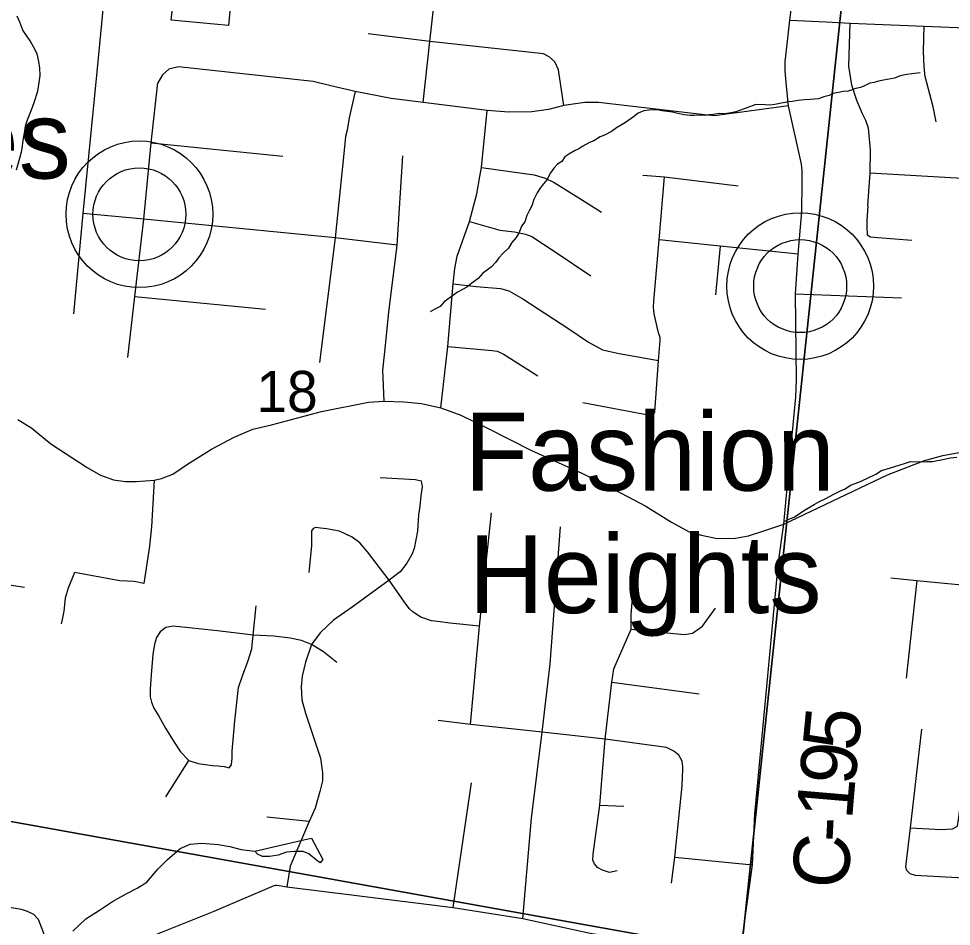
# Model space of a CAD drawing. Extents: x 0 to 43.4, y -8.1 to 22.
# Drawn here: x 6.917 to 7.863, y 16.255 to 17.176 of the extents above; entities that cross this region are included whole.
import ezdxf

# ---------------------------------------------------------------- set-up
doc = ezdxf.new("R2010")
doc.units = 0
for name, color, linetype in [('GM_X_City_Street', 7, 'Continuous'), ('GM_X_Corporation', 7, 'Continuous'), ('GM_X_County_Road', 7, 'Continuous'), ('GM_X_County_Road_Text', 7, 'Continuous'), ('GM_X_Minor_Lake', 7, 'Continuous'), ('GM_X_Minor_River', 7, 'Continuous'), ('GM_X_Section_Text', 7, 'Continuous'), ('GM_X_Township_Road', 7, 'Continuous'), ('GM_X_Unincorporated', 7, 'Continuous'), ('GM_X_Unincorporated_Location', 7, 'Continuous'), ('GM_X_Unincorporated_Text', 7, 'Continuous')]:
    doc.layers.add(name, color=color, linetype=linetype)

msp = doc.modelspace()

# ---------------------------------------------------------------- linework, layer by layer
at = {"layer": 'GM_X_City_Street'}
for points in [[(7.73626, 17.17249), (7.76063, 17.17115), (7.83577, 17.16785), (7.88622, 17.16592), (7.96008, 17.16294), (8.00847, 17.16036), (8.09018, 17.15672), (8.11414, 17.15544)], [(7.77863, 16.98558), (7.78106, 17.01914), (7.78137, 17.04256), (7.77909, 17.06442), (7.77635, 17.07212), (7.77304, 17.07888), (7.76723, 17.0924), (7.76235, 17.10796), (7.75937, 17.12729), (7.76, 17.14954), (7.76063, 17.17115)], [(7.84777, 17.07077), (7.84486, 17.08605), (7.83671, 17.11692), (7.83561, 17.12682), (7.83498, 17.14254), (7.83577, 17.16785)], [(7.78106, 17.01914), (7.90336, 17.01203), (8.00934, 17.00692), (8.1949, 17.0006)]]:
    msp.add_lwpolyline(points, dxfattribs=at)
at = {"layer": 'GM_X_Corporation'}
for points in [[(7.75749, 17.24308), (7.65014, 16.22803), (6.62666, 16.41193), (6.72714, 17.35166)], [(7.75749, 17.24308), (8.74847, 17.1931), (8.6363, 16.19901), (7.65014, 16.22803)], [(7.65014, 16.22803), (7.54379, 15.2065), (6.51942, 15.39622), (6.62666, 16.41193)]]:
    msp.add_lwpolyline(points, close=True, dxfattribs=at)
at = {"layer": 'GM_X_County_Road'}
for points in [[(7.69325, 16.66276), (7.69899, 16.72496), (7.70539, 16.79174), (7.70605, 16.80885), (7.70507, 16.89638), (7.70788, 16.93665), (7.71154, 16.97964), (7.71187, 17.00934), (7.71193, 17.0212), (7.71128, 17.02799), (7.69808, 17.08718), (7.69612, 17.10717), (7.69454, 17.12252), (7.69459, 17.13174), (7.69716, 17.15265), (7.69923, 17.17421), (7.702, 17.19538), (7.70331, 17.21681), (7.70697, 17.24634)], [(6.91604, 16.76883), (6.93026, 16.76018), (6.94963, 16.7442), (6.98628, 16.72027), (7.00013, 16.71238), (7.01331, 16.70793), (7.02541, 16.70614), (7.03602, 16.70591), (7.05445, 16.70741), (7.06188, 16.70914), (7.07336, 16.71344), (7.08837, 16.72374), (7.1126, 16.73876), (7.13563, 16.75115), (7.15439, 16.75909), (7.17345, 16.76361), (7.22418, 16.77698), (7.27172, 16.78647), (7.28795, 16.78756), (7.30777, 16.78701), (7.3258, 16.78527), (7.34544, 16.78064), (7.36548, 16.77341), (7.39279, 16.76005), (7.43714, 16.73737), (7.48837, 16.71448), (7.52179, 16.69768), (7.55343, 16.68095), (7.57917, 16.66469), (7.59712, 16.6551), (7.60993, 16.65172), (7.62577, 16.64825), (7.64437, 16.64851), (7.65733, 16.65082), (7.67302, 16.65609), (7.69325, 16.66276), (7.79836, 16.71285), (7.83608, 16.72746), (7.85463, 16.73249), (7.87491, 16.73611)], [(7.58249, 15.6055), (7.58756, 15.65514), (7.59384, 15.71421), (7.5992, 15.76453), (7.61792, 15.94053), (7.62113, 15.97245), (7.63242, 16.08479), (7.63341, 16.09461), (7.64876, 16.22421), (7.66156, 16.31734), (7.66386, 16.36899), (7.67012, 16.43335), (7.68774, 16.62457), (7.69325, 16.66276)], [(6.90828, 16.17393), (6.92096, 16.18174), (6.93139, 16.19106), (6.94814, 16.2), (7.02566, 16.23433), (7.1152, 16.27031), (7.17607, 16.29629), (7.17739, 16.29672), (7.17871, 16.29671), (7.18117, 16.29638), (7.18894, 16.29488), (7.25726, 16.28656), (7.35784, 16.27411), (7.42833, 16.26272), (7.49667, 16.24803), (7.64876, 16.22421), (7.66742, 16.22237), (7.66839, 16.22235)]]:
    msp.add_lwpolyline(points, dxfattribs=at)
at = {"layer": 'GM_X_Minor_Lake'}
for points in [[(7.15655, 16.33123), (7.20747, 16.34286), (7.21396, 16.34421), (7.21686, 16.33919), (7.22553, 16.32263), (7.22278, 16.31929), (7.21906, 16.32204), (7.21125, 16.32833), (7.20563, 16.33076), (7.19689, 16.33061), (7.18853, 16.33007), (7.18009, 16.32688)], [(7.18009, 16.32688), (7.17132, 16.32559), (7.1645, 16.32577), (7.15925, 16.32819), (7.15655, 16.33123)]]:
    msp.add_lwpolyline(points, dxfattribs=at)
at = {"layer": 'GM_X_Minor_River'}
for points in [[(6.91477, 17.02231), (6.91804, 17.03404), (6.9201, 17.04198), (6.92184, 17.05412), (6.92312, 17.06132), (6.92399, 17.067), (6.92601, 17.07305), (6.93001, 17.08324), (6.93282, 17.09041), (6.93647, 17.10213), (6.93777, 17.11085), (6.93867, 17.11806), (6.93842, 17.12528), (6.9374, 17.13214), (6.93563, 17.13978), (6.93194, 17.14707), (6.92862, 17.15321), (6.92117, 17.16399), (6.91827, 17.17202), (6.91532, 17.17816)], [(7.83149, 17.12047), (7.8231, 17.11956), (7.81814, 17.11894), (7.81126, 17.11761), (7.80549, 17.1151), (7.7944, 17.11313), (7.78943, 17.11212), (7.78483, 17.11073), (7.78063, 17.11008), (7.77524, 17.10757), (7.77101, 17.10578), (7.76642, 17.10477), (7.75873, 17.10193), (7.7534, 17.1017), (7.74881, 17.10069), (7.74346, 17.09969), (7.73922, 17.09753), (7.73386, 17.09615), (7.72849, 17.0944), (7.72047, 17.09348), (7.71439, 17.09327), (7.70752, 17.0927), (7.70217, 17.09171), (7.69797, 17.09106), (7.68918, 17.0894), (7.68421, 17.0884), (7.67925, 17.08778), (7.67432, 17.0883), (7.66482, 17.08856), (7.6556, 17.08501), (7.64945, 17.0829), (7.64446, 17.08113), (7.63987, 17.08012), (7.633, 17.07917), (7.62844, 17.07929), (7.62157, 17.07834), (7.61738, 17.07808), (7.61318, 17.07744), (7.60786, 17.07758), (7.60253, 17.07735), (7.59835, 17.07747), (7.59228, 17.07802), (7.58585, 17.07934), (7.58018, 17.08064), (7.57488, 17.08155), (7.56957, 17.08208), (7.56541, 17.08296), (7.56123, 17.08308), (7.55628, 17.08283), (7.55132, 17.08221), (7.54555, 17.07971), (7.54089, 17.07603), (7.53274, 17.07016), (7.52772, 17.06725), (7.52346, 17.06471), (7.51842, 17.06104), (7.51148, 17.05743), (7.50687, 17.05565), (7.50067, 17.05163), (7.49606, 17.04986), (7.4895, 17.04623), (7.48525, 17.04368), (7.481, 17.04152), (7.47521, 17.03825), (7.47095, 17.03532), (7.46816, 17.03083), (7.46352, 17.02791), (7.45999, 17.02382), (7.45645, 17.01935), (7.45283, 17.01221), (7.4493, 17.00813), (7.44574, 17.00327), (7.44296, 16.99878), (7.43973, 16.99201), (7.43766, 16.9856), (7.43486, 16.98072), (7.43245, 16.97584), (7.43037, 16.96942), (7.42721, 16.96494), (7.42475, 16.95853), (7.42158, 16.95367), (7.41725, 16.94846), (7.41406, 16.94284), (7.4086, 16.93766), (7.40428, 16.93282), (7.40074, 16.92836), (7.39681, 16.92389), (7.39255, 16.92096), (7.38789, 16.91728), (7.38318, 16.91209), (7.37659, 16.90732), (7.37153, 16.90327), (7.36728, 16.90072), (7.36227, 16.8982), (7.3549, 16.89269), (7.34869, 16.88829), (7.34476, 16.88345), (7.33936, 16.88094), (7.33434, 16.87803)], [(7.69365, 16.66536), (7.69829, 16.6679), (7.70367, 16.67003), (7.71412, 16.67698), (7.72417, 16.68279), (7.7288, 16.68533), (7.73652, 16.6893), (7.74346, 16.69292), (7.75078, 16.69652), (7.7554, 16.69868), (7.76083, 16.70233), (7.76928, 16.70553), (7.77736, 16.70911), (7.78661, 16.71342), (7.79241, 16.71707), (7.80161, 16.71986), (7.81121, 16.72302), (7.81581, 16.72441), (7.82195, 16.72653), (7.83068, 16.7259), (7.8383, 16.72645), (7.844, 16.72629), (7.8547, 16.72828), (7.86197, 16.72998), (7.86884, 16.73093)], [(6.97193, 16.25003), (6.98515, 16.26261), (6.99904, 16.27138), (7.01217, 16.28016), (7.02602, 16.28779), (7.03718, 16.29359), (7.04682, 16.2998), (7.05816, 16.31281), (7.06751, 16.32245), (7.08071, 16.33389), (7.09107, 16.33819), (7.10285, 16.33904), (7.11952, 16.33786), (7.13123, 16.33567), (7.14254, 16.33272), (7.15655, 16.33123)]]:
    msp.add_lwpolyline(points, dxfattribs=at)
at = {"layer": 'GM_X_Township_Road'}
for p, q in [((7.69923, 17.17421), (7.73626, 17.17249)), ((7.05146, 17.04952), (7.18489, 17.03626)), ((7.62862, 16.94467), (7.62401, 16.89541)), ((7.03488, 16.8938), (7.16721, 16.88081)), ((7.70507, 16.89638), (7.81257, 16.89225)), ((7.82809, 16.60582), (7.81726, 16.50658)), ((7.51869, 16.50256), (7.60747, 16.49064)), ((7.06617, 16.38629), (7.08955, 16.42317)), ((7.35784, 16.27411), (7.37623, 16.40032)), ((7.5065, 16.37784), (7.53079, 16.37669)), ((7.21167, 16.36131), (7.1686, 16.36563)), ((7.58274, 16.32517), (7.66156, 16.31734))]:
    msp.add_line(p, q, dxfattribs=at)
for points in [[(7.01941, 17.32209), (7.00508, 17.21329), (7.00263, 17.18831), (6.99624, 17.1217), (6.98211, 16.97805), (6.97254, 16.87602)], [(7.14594, 17.30847), (7.14115, 17.2755), (7.13544, 17.23351), (7.13305, 17.20459), (7.12968, 17.16861), (7.0718, 17.17415), (7.08572, 17.29872)], [(7.32745, 17.0905), (7.33417, 17.15229), (7.3408, 17.21251), (7.34909, 17.28618)], [(7.47009, 17.08746), (7.46475, 17.12355), (7.46106, 17.13166), (7.45535, 17.13681), (7.44928, 17.13995), (7.33417, 17.15229), (7.27155, 17.1602)], [(7.69808, 17.08718), (7.65078, 17.08085), (7.63258, 17.07822), (7.62358, 17.0769), (7.61602, 17.07767), (7.50516, 17.09068), (7.49146, 17.0904), (7.47009, 17.08746), (7.45454, 17.08335), (7.43776, 17.08111), (7.41423, 17.0806), (7.39237, 17.08248), (7.32745, 17.0905), (7.29485, 17.09464), (7.25838, 17.10173), (7.23361, 17.10753), (7.21565, 17.11167), (7.07899, 17.12669), (7.06942, 17.12429), (7.06279, 17.11876), (7.05818, 17.11057)], [(7.0278, 16.83201), (7.03488, 16.8938), (7.04379, 16.97218), (7.05146, 17.04952), (7.05818, 17.11057)], [(7.25838, 17.10173), (7.2523, 17.07512), (7.25009, 17.06232), (7.24853, 17.05605), (7.24669, 17.03884), (7.23794, 16.95319), (7.22224, 16.82664)], [(7.34544, 16.78064), (7.35239, 16.84294), (7.35796, 16.90647), (7.35933, 16.92221), (7.36185, 16.93455), (7.37446, 16.96975), (7.38181, 16.99772), (7.38488, 17.01537), (7.38665, 17.02466), (7.39237, 17.08248)], [(7.28795, 16.78756), (7.28656, 16.81891), (7.28832, 16.83759), (7.29237, 16.87794), (7.30082, 16.9459), (7.30683, 17.03643)], [(7.38665, 17.02466), (7.44003, 17.01732), (7.45113, 17.01379), (7.46029, 17.00939), (7.48531, 16.99388), (7.50839, 16.97943)], [(7.55024, 17.01696), (7.57227, 17.01508), (7.64695, 17.00602)], [(7.48947, 16.78629), (7.55741, 16.77346), (7.55919, 16.7736), (7.56084, 16.77413), (7.56185, 16.77515), (7.56242, 16.77636), (7.56628, 16.82872), (7.56777, 16.84909), (7.56779, 16.85108), (7.56772, 16.85225), (7.56751, 16.85328), (7.566, 16.85699), (7.56162, 16.8762), (7.56118, 16.883), (7.56151, 16.88903), (7.56688, 16.9511), (7.57227, 17.01508)], [(7.30082, 16.9459), (7.23794, 16.95319), (7.04379, 16.97218), (6.98211, 16.97805)], [(7.77863, 16.98558), (7.77768, 16.97088), (7.77752, 16.96428), (7.77784, 16.95634), (7.78114, 16.95422), (7.78853, 16.95351), (7.82314, 16.95078)], [(7.37446, 16.96975), (7.40514, 16.96102), (7.42012, 16.95944), (7.43131, 16.95714), (7.43765, 16.95459), (7.46135, 16.93917), (7.49745, 16.91476)], [(7.70788, 16.93665), (7.62862, 16.94467), (7.56688, 16.9511)], [(7.35796, 16.90647), (7.38107, 16.90385), (7.40578, 16.90197), (7.41422, 16.89945), (7.42848, 16.89122), (7.47531, 16.86084), (7.49505, 16.84758), (7.50931, 16.83979), (7.5263, 16.83595), (7.56628, 16.82872)], [(7.35239, 16.84294), (7.39725, 16.83902), (7.40231, 16.83821), (7.40495, 16.8374), (7.4094, 16.83497), (7.44382, 16.8131)], [(7.05445, 16.70741), (7.05182, 16.66012), (7.04968, 16.64054), (7.04399, 16.60247), (7.03402, 16.6046), (7.01943, 16.60531), (6.97353, 16.61386), (6.96703, 16.59789), (6.96413, 16.58773), (6.96268, 16.57467), (6.96123, 16.56597), (6.95994, 16.56167)], [(7.28373, 16.71007), (7.31973, 16.70825), (7.32549, 16.70673), (7.32626, 16.70066), (7.32512, 16.69159), (7.32383, 16.68121), (7.32261, 16.67225), (7.32155, 16.65554), (7.31813, 16.63808), (7.31593, 16.63216), (7.31092, 16.62334), (7.30393, 16.61461), (7.29269, 16.60611), (7.25533, 16.57877), (7.2365, 16.5654), (7.22297, 16.5525), (7.21399, 16.5406), (7.20786, 16.52293), (7.20454, 16.5085), (7.20364, 16.49784), (7.2041, 16.48456), (7.20798, 16.4712), (7.22329, 16.42536), (7.22535, 16.41044), (7.22506, 16.40256), (7.22254, 16.39162), (7.21762, 16.37466), (7.21167, 16.36131), (7.19243, 16.31604), (7.18894, 16.29488)], [(6.65201, 16.68027), (6.73099, 16.66696), (6.72532, 16.63915), (6.72478, 16.63434), (6.73048, 16.63336), (6.82658, 16.61706), (6.90281, 16.60206), (6.92292, 16.59878)], [(7.37528, 16.4596), (7.38454, 16.55923), (7.39681, 16.67417)], [(7.34471, 16.5636), (7.3359, 16.56472), (7.32512, 16.56859), (7.31714, 16.5736), (7.31327, 16.57718), (7.30849, 16.58355), (7.29269, 16.60611), (7.27097, 16.63473), (7.26323, 16.6437), (7.25533, 16.64962), (7.24242, 16.65554), (7.22928, 16.65805), (7.22306, 16.65873), (7.21858, 16.65927), (7.21569, 16.65828), (7.21394, 16.656), (7.21409, 16.65144), (7.21403, 16.64117), (7.21151, 16.61393)], [(7.42833, 16.26272), (7.43725, 16.36446), (7.44804, 16.45176), (7.45606, 16.52107), (7.46676, 16.66012)], [(7.52412, 16.31103), (7.51647, 16.3096), (7.50917, 16.31192), (7.50419, 16.31468), (7.50116, 16.31823), (7.49956, 16.32206), (7.49983, 16.3282), (7.5065, 16.37784), (7.5121, 16.44483), (7.51869, 16.50256), (7.52065, 16.51618), (7.53826, 16.55639), (7.53844, 16.57098), (7.54111, 16.6046)], [(7.80181, 16.60839), (7.82809, 16.60582), (7.84928, 16.60377)], [(7.84928, 16.60377), (7.88107, 16.6007), (7.92956, 16.59431), (7.97476, 16.58834), (7.99966, 16.58504)], [(7.12186, 16.4173), (7.12543, 16.41708), (7.13056, 16.41571), (7.13282, 16.41865), (7.13344, 16.4256), (7.13356, 16.43262), (7.13632, 16.46322), (7.1399, 16.49695), (7.144, 16.5088), (7.14982, 16.52434), (7.15355, 16.5362), (7.1549, 16.55027), (7.15795, 16.57986)], [(7.53826, 16.55639), (7.58167, 16.55194), (7.59253, 16.55087), (7.60053, 16.55229), (7.61085, 16.55941), (7.62384, 16.57774)], [(7.38454, 16.55923), (7.35451, 16.56236), (7.34471, 16.5636)], [(7.23963, 16.52258), (7.22619, 16.5332), (7.21399, 16.5406), (7.20405, 16.54467), (7.19224, 16.54727), (7.17592, 16.54902), (7.1549, 16.55027), (7.11881, 16.55467), (7.07362, 16.55919), (7.06628, 16.55795), (7.06041, 16.55343), (7.05668, 16.54767), (7.05478, 16.54091), (7.05295, 16.53072), (7.05148, 16.51004), (7.05023, 16.49547), (7.05035, 16.48768), (7.05159, 16.48214), (7.05419, 16.47627), (7.05916, 16.46791), (7.06594, 16.45582), (7.07475, 16.44159), (7.0813, 16.43176), (7.08955, 16.42317), (7.09899, 16.42018), (7.10638, 16.41894), (7.11367, 16.41803), (7.11921, 16.41758), (7.12186, 16.4173)], [(7.57931, 16.29874), (7.58274, 16.32517), (7.59004, 16.39732), (7.59039, 16.40711), (7.59075, 16.41298), (7.59075, 16.41689), (7.59004, 16.42241), (7.58684, 16.42846), (7.58185, 16.43255), (7.57438, 16.43611), (7.5121, 16.44483), (7.44804, 16.45176), (7.37528, 16.4596), (7.34254, 16.46351)], [(7.83289, 16.45472), (7.82142, 16.35463), (7.81682, 16.31515), (7.81787, 16.3117), (7.8212, 16.30857), (7.82647, 16.30691), (7.89446, 16.30319), (7.90044, 16.30286)], [(7.82142, 16.35463), (7.85296, 16.35309), (7.86443, 16.35387), (7.86963, 16.35647), (7.87068, 16.36325), (7.87198, 16.37315), (7.87928, 16.45159)], [(6.85221, 16.28406), (6.85813, 16.28252), (6.86318, 16.28143), (6.87239, 16.28055), (6.89213, 16.27704), (6.90792, 16.27441), (6.91954, 16.27222), (6.92568, 16.27024), (6.93183, 16.26717), (6.93665, 16.26213), (6.94191, 16.24897), (6.94433, 16.2391), (6.94586, 16.23054), (6.94389, 16.22287), (6.94257, 16.21651), (6.94323, 16.20817), (6.94564, 16.20444), (6.94814, 16.2)]]:
    msp.add_lwpolyline(points, dxfattribs=at)
at = {"layer": 'GM_X_Unincorporated'}
for centre, radius in [((7.03944, 16.97713), 0.0744), ((7.03944, 16.97713), 0.04716), ((7.70988, 16.90425), 0.0744), ((7.70988, 16.90425), 0.04716)]:
    msp.add_circle(centre, radius, dxfattribs=at)
at = {"layer": 'GM_X_Unincorporated_Location'}
for p, q in [((7.03944, 16.97713), (7.03944, 16.97713)), ((7.70988, 16.90425), (7.70988, 16.90425))]:
    msp.add_line(p, q, dxfattribs=at)

# ---------------------------------------------------------------- texts
at = {"layer": 'GM_X_County_Road_Text'}
for s, rotation, p in [('5', 84.46752, (7.76874, 16.4317)), ('9', 84.58507, (7.76544, 16.39689)), ('1', 85.13112, (7.76248, 16.36216)), ('-', 87.04482, (7.76132, 16.33935)), ('C', 86.46164, (7.7584, 16.29215))]:
    msp.add_text(s, height=0.05682, rotation=rotation, dxfattribs=at).set_placement(p)
at = {"layer": 'GM_X_Section_Text'}
msp.add_text('18', height=0.041856, rotation=0.00001, dxfattribs=at).set_placement((7.15809, 16.77648))
at = {"layer": 'GM_X_Unincorporated_Text'}
for s, p in [('The Pines', (6.49434, 17.01346)), ('Fashion', (7.36934, 16.69679)), ('Heights', (7.3735, 16.57262))]:
    msp.add_text(s, height=0.078977, rotation=0.00001, dxfattribs=at).set_placement(p)

doc.saveas('drawing.dxf')
